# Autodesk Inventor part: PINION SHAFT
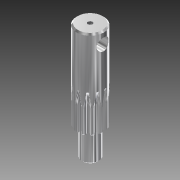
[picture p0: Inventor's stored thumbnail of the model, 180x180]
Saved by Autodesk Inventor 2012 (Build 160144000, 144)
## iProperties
Shininess: 64.0
Length Units: 11269
Angle Units: 11279
Time Units: 11290
Mass Units: 11283
Length Display Precision: 3
Angle Display Precision: 2
Compacted: True
Part Number: PINION SHAFT
Document SubType Name: Modeling
Created: 2003-10
Designer: Autodesk, Inc.
Manufacturer: Standard
Standards Organization: Custom
Mass: 506.446 g
Surface Area: 152.229 cm^2
Volume: 64.5977 cm^3
Density: 7.84 g/cm^3
Material: Steel, High Strength Low Alloy
Density: 0.0
Volumn: 0.0
Area: 0.0
PropertySet Name: Model Information
Control State: 0
Master: False
Checked Out: False
Author: Autodesk, Inc.
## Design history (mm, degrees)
sketch "Sketch1" dims "d4" = 6.7945 (= Big_R), "d5" = 5.54567 (= 2 x little_r)
  geometry: L1 (0, 12.7)-(5.815, 12.7); L2 (5.815, 12.7)-(5.815, 14.817); L3 (5.815, 14.817)-(0, 14.817); L4 (0, 14.817)-(0, 12.7); L5 (-8.163, 9.729)-(5.815, 14.817); L6 (0, 0)-(0, 10.251); L7 (0, 11.934)-(0, 12.7); L8 (0, 11.934)-(0, 10.251); L9 (-0.191, 11.933)-(-0.184, 10.731); L10 (0, 0)-(1.934, 14.69); L11 (0, 0)-(-1.338, 10.163); L12 (0, 0)-(3.923, 9.471); L13 (3.273, 11.477)-(2.955, 10.318); L14 (-0.181, 10.249)-(-0.184, 10.731); A1 r 12.7 centre (0, 0) between (0, 12.7) and (-8.163, 9.729); A2 r 14.817 centre (0, 0) between (0, 14.817) and (1.934, 14.69); A3 r 11.934 centre (0, 0) between (0, 11.934) and (6.294, 10.14); A4 r 10.251 centre (0, 0) between (0, 10.251) and (-0.181, 10.249); A5 r 6.795 centre (6.294, 10.14) between (1.365, 14.817) and (0, 12.7); A6 r 2.773 centre (2.568, 11.654) between (0, 12.7) and (-0.191, 11.933); A7 r 10.251 centre (0, 0) between (-0.651, 10.23) and (-1.338, 10.163); A8 r 0.498 centre (-0.682, 10.728) between (-0.651, 10.23) and (-0.184, 10.731); A9 r 10.251 centre (0, 0) between (3.923, 9.471) and (3.276, 9.713); A10 r 0.498 centre (3.435, 10.186) between (2.955, 10.318) and (3.276, 9.713); A11 r 2.773 centre (0.536, 11.922) between (3.273, 11.477) and (3.287, 12.267); A12 r 6.795 centre (-3.455, 11.423) between (3.287, 12.267) and (2.516, 14.665); A13 r 14.879 centre (0, 0) between (2.516, 14.665) and (1.365, 14.817); 2 further points; 1 other entity
  constraints: 30 point on circle, 28 end point, 13 centre point, 9 coincident, 9 symmetric about line, 4 tangent, 3 point on line, 2 parallel, 2 vertical, 1 collinear, 1 horizontal, 1 perpendicular, 16 other
  dimensions: "d0" = 25.4 diameter of A1 (= Pitch_Diameter); "d1" = 2.11667 distance of L1.end L2.end (= Addendum); "d2" = 20 deg angle of L1 L5 (= Tooth_Form); "d3" = 4.56565 distance of L6.end L3.end (= Whole_Depth); "d6" = 7.5 deg angle of L10 L6 (= mirror_angle); "d7" = 7.5 deg angle of L11 L6 (= mirror_angle); "d8" = 0.49848 radius of A8 (= Root_Fillet)
extrude "Extrusion1" new body sketch "Sketch1" distance "d9" = 25.4; taper "d10" = 0 deg
pattern_circular "Circular Pattern1" dims angle "d13" = 360 deg
sketch "Sketch2"
  geometry: C1 r 14.879 at (0, 0); 1 further point
  constraints: 1 centre point, 1 coincident
  dimensions: "d14" = 29.758 diameter of C1
extrude "Extrusion2" join sketch "Sketch2" distance "d15" = 71.4502; taper "d16" = 0 deg
sketch "Sketch3"
  geometry: C1 r 9.5 at (0, 0); 1 further point
  constraints: 1 centre point, 1 coincident
  dimensions: "d17" = 18.9992 diameter of C1
extrude "Extrusion3" join sketch "Sketch3" distance "d18" = 30.1498; taper "d19" = 0 deg
chamfer "Chamfer1" distance "d20" = 1.5875; stored, may be unused: second distance "d21" = 2, angle "d67" = 45 deg
chamfer "Chamfer2" distance "d22" = 1.5875; stored, may be unused: second distance "d23" = 2, angle "d68" = 45 deg
workplane "Work Plane2"
sketch "Sketch4"
  geometry: L1 (-13.292, 96.85)-(13.292, 96.85) reference; L2 (0, 96.85)-(0, 65.832); C1 r 6.54 at (0, 84.15)
  constraints: 2 end point, 1 centre point, 1 midpoint, 1 perpendicular, 1 point on line
  dimensions: "d26" = 13.081 diameter of C1; "d27" = 12.7 distance from line of L1 C1.centre
extrude "Extrusion4" cut sketch "Sketch4" distance "d28" = 50.8; taper "d29" = 0 deg
workplane "Work Plane3"
sketch "Sketch10"
  geometry: L1 (-5.206, 9.385)-(-5.801, 10.429) reference; L2 (-3.273, 11.477)-(-2.955, 10.318) reference; L3 (-5.801, 10.429)-(-5.206, 9.385); L4 (-2.955, 10.318)-(-3.273, 11.477); L5 (-30.301, 30.745)-(3.482, 44.738); L6 (-8.59, 12.149)-(-2.517, 14.665); L7 (0.184, 10.731)-(0.191, 11.933) reference; L8 (2.904, 11.575)-(2.6, 10.413) reference; L9 (0.191, 11.933)-(0.184, 10.731); L10 (2.904, 11.575)-(2.6, 10.413); L11 (5.524, 9.201)-(6.131, 10.239) reference; L12 (8.303, 8.572)-(7.458, 7.718) reference; L13 (5.524, 9.201)-(6.131, 10.239); L14 (7.458, 7.718)-(8.303, 8.572); L15 (9.385, 5.206)-(10.429, 5.801) reference; L16 (11.477, 3.273)-(10.318, 2.955) reference; L17 (9.385, 5.206)-(10.429, 5.801); L18 (11.477, 3.273)-(10.318, 2.955); A1 r 6.795 centre (3.455, 11.423) between (-2.517, 14.665) and (-3.287, 12.267) reference; A2 r 14.879 centre (0, 0) between (-2.517, 14.665) and (-8.59, 12.149) reference; A3 r 6.795 centre (-10.52, 5.634) between (-6.35, 10.999) and (-8.59, 12.149) reference; A4 r 2.773 centre (-8.051, 8.809) between (-5.801, 10.429) and (-6.35, 10.999) reference; A5 r 0.498 centre (-4.773, 9.632) between (-5.206, 9.385) and (-4.552, 9.185) reference; A6 r 10.251 centre (0, 0) between (-3.276, 9.713) and (-4.552, 9.185) reference; A7 r 0.498 centre (-3.435, 10.186) between (-3.276, 9.713) and (-2.955, 10.318) reference; A8 r 2.773 centre (-0.536, 11.922) between (-3.287, 12.267) and (-3.273, 11.477) reference; A9 r 14.879 centre (0, 0) between (-2.517, 14.665) and (-8.59, 12.149); A10 r 6.795 centre (-10.52, 5.634) between (-6.35, 10.999) and (-8.59, 12.149); A11 r 2.773 centre (-8.051, 8.809) between (-5.801, 10.429) and (-6.35, 10.999); A12 r 0.498 centre (-4.773, 9.632) between (-5.206, 9.385) and (-4.552, 9.185); A13 r 10.251 centre (0, 0) between (-3.276, 9.713) and (-4.552, 9.185); A14 r 6.795 centre (3.455, 11.423) between (-2.517, 14.665) and (-3.287, 12.267); A15 r 2.773 centre (-0.536, 11.922) between (-3.287, 12.267) and (-3.273, 11.477); A16 r 0.498 centre (-3.435, 10.186) between (-3.276, 9.713) and (-2.955, 10.318); A17 r 10.251 centre (0, 0) between (-3.276, 9.713) and (-4.552, 9.185) reference; A18 r 6.795 centre (8.704, 8.165) between (5.153, 13.958) and (3.287, 12.267) reference; A19 r 14.879 centre (0, 0) between (5.153, 13.958) and (-1.365, 14.816) reference; A20 r 6.795 centre (-6.294, 10.14) between (0, 12.7) and (-1.365, 14.816) reference; A21 r 2.773 centre (-2.568, 11.654) between (0.191, 11.933) and (0, 12.7) reference; A22 r 0.498 centre (0.682, 10.728) between (0.184, 10.731) and (0.651, 10.23) reference; A23 r 10.251 centre (0, 0) between (2.019, 10.05) and (0.651, 10.23) reference; A24 r 0.498 centre (2.118, 10.539) between (2.019, 10.05) and (2.6, 10.413) reference; A25 r 2.773 centre (5.497, 10.593) between (3.287, 12.267) and (2.904, 11.575) reference; A26 r 6.795 centre (-6.294, 10.14) between (0, 12.7) and (-1.365, 14.816); A27 r 2.773 centre (-2.568, 11.654) between (0.191, 11.933) and (0, 12.7); A28 r 0.498 centre (0.682, 10.728) between (0.184, 10.731) and (0.651, 10.23); A29 r 0.498 centre (2.118, 10.539) between (2.019, 10.05) and (2.6, 10.413); A30 r 2.773 centre (5.497, 10.593) between (3.287, 12.267) and (2.904, 11.575); A31 r 6.795 centre (8.704, 8.165) between (5.153, 13.958) and (3.287, 12.267); A32 r 14.879 centre (0, 0) between (5.153, 13.958) and (-1.365, 14.816); A33 r 10.251 centre (0, 0) between (2.019, 10.05) and (0.651, 10.23); A34 r 6.795 centre (11.62, 2.72) between (11.442, 9.512) and (8.98, 8.98) reference; A35 r 14.879 centre (0, 0) between (11.442, 9.512) and (6.226, 13.514) reference; A36 r 6.795 centre (-0.381, 11.928) between (6.35, 10.999) and (6.226, 13.514) reference; A37 r 2.773 centre (3.603, 11.377) between (6.131, 10.239) and (6.35, 10.999) reference; A38 r 0.498 centre (5.955, 8.949) between (5.524, 9.201) and (5.679, 8.534) reference; A39 r 10.251 centre (0, 0) between (6.774, 7.694) and (5.679, 8.534) reference; A40 r 0.498 centre (7.103, 8.068) between (6.774, 7.694) and (7.458, 7.718) reference; A41 r 2.773 centre (10.057, 6.425) between (8.98, 8.98) and (8.303, 8.572) reference; A42 r 14.879 centre (0, 0) between (11.442, 9.512) and (6.226, 13.514); A43 r 6.795 centre (-0.381, 11.928) between (6.35, 10.999) and (6.226, 13.514); A44 r 2.773 centre (3.603, 11.377) between (6.131, 10.239) and (6.35, 10.999); A45 r 0.498 centre (5.955, 8.949) between (5.524, 9.201) and (5.679, 8.534); A46 r 0.498 centre (7.103, 8.068) between (6.774, 7.694) and (7.458, 7.718); A47 r 2.773 centre (10.057, 6.425) between (8.98, 8.98) and (8.303, 8.572); A48 r 6.795 centre (11.62, 2.72) between (11.442, 9.512) and (8.98, 8.98); A49 r 10.251 centre (0, 0) between (6.774, 7.694) and (5.679, 8.534); A50 r 6.795 centre (11.423, -3.455) between (14.665, 2.517) and (12.267, 3.287) reference; A51 r 14.879 centre (0, 0) between (14.665, 2.517) and (12.149, 8.59) reference; A52 r 6.795 centre (5.634, 10.52) between (10.999, 6.35) and (12.149, 8.59) reference; A53 r 2.773 centre (8.809, 8.051) between (10.429, 5.801) and (10.999, 6.35) reference; A54 r 0.498 centre (9.632, 4.773) between (9.385, 5.206) and (9.185, 4.552) reference; A55 r 10.251 centre (0, 0) between (9.713, 3.276) and (9.185, 4.552) reference; A56 r 0.498 centre (10.186, 3.435) between (9.713, 3.276) and (10.318, 2.955) reference; A57 r 2.773 centre (11.922, 0.536) between (12.267, 3.287) and (11.477, 3.273) reference; A58 r 10.251 centre (0, 0) between (9.713, 3.276) and (9.185, 4.552); A59 r 0.498 centre (9.632, 4.773) between (9.385, 5.206) and (9.185, 4.552); A60 r 0.498 centre (10.186, 3.435) between (9.713, 3.276) and (10.318, 2.955); A61 r 2.773 centre (11.922, 0.536) between (12.267, 3.287) and (11.477, 3.273); A62 r 2.773 centre (8.809, 8.051) between (10.429, 5.801) and (10.999, 6.35); A63 r 6.795 centre (5.634, 10.52) between (10.999, 6.35) and (12.149, 8.59); A64 r 6.794 centre (11.423, -3.455) between (14.665, 2.517) and (12.267, 3.287)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
  constraints: 66 point on circle, 32 centre point, 30 concentric, 27 tangent, 20 end point, 8 collinear, 1 parallel
  dimensions: "d32" = 40 distance from line of L5 A17.centre
revolve "Revolution1" sketch "Sketch10" stored, may be unused: angle "d33" = 90 deg
sketch "Sketch11"
  geometry: L1 (0.184, 10.731)-(0.191, 11.933) reference; L2 (2.904, 11.575)-(2.6, 10.413) reference; L3 (0.184, 10.731)-(0.191, 11.933); L4 (2.6, 10.413)-(2.904, 11.575); L5 (-8.56, 41.472)-(25.088, 37.042); L6 (-1.365, 14.816)-(5.153, 13.958); C1 r 7.912 at (0, 0) reference; A1 r 6.795 centre (8.704, 8.165) between (5.153, 13.958) and (3.287, 12.267) reference; A2 r 14.879 centre (0, 0) between (5.153, 13.958) and (-1.365, 14.816) reference; A3 r 6.795 centre (-6.294, 10.14) between (0, 12.7) and (-1.365, 14.816) reference; A4 r 2.773 centre (-2.568, 11.654) between (0.191, 11.933) and (0, 12.7) reference; A5 r 0.498 centre (0.682, 10.728) between (0.184, 10.731) and (0.651, 10.23) reference; A6 r 10.251 centre (0, 0) between (2.019, 10.05) and (0.651, 10.23) reference; A7 r 0.498 centre (2.118, 10.539) between (2.019, 10.05) and (2.6, 10.413) reference; A8 r 2.773 centre (5.497, 10.593) between (3.287, 12.267) and (2.904, 11.575) reference; A9 r 14.879 centre (0, 0) between (5.153, 13.958) and (-1.365, 14.816); A10 r 6.795 centre (-6.294, 10.14) between (0, 12.7) and (-1.365, 14.816); A11 r 2.773 centre (-2.568, 11.654) between (0.191, 11.933) and (0, 12.7); A12 r 0.498 centre (0.682, 10.728) between (0.184, 10.731) and (0.651, 10.23); A13 r 10.251 centre (0, 0) between (2.019, 10.05) and (0.651, 10.23); A14 r 6.795 centre (8.704, 8.165) between (5.153, 13.958) and (3.287, 12.267); A15 r 2.773 centre (5.497, 10.593) between (3.287, 12.267) and (2.904, 11.575); A16 r 0.498 centre (2.118, 10.539) between (2.019, 10.05) and (2.6, 10.413)
  constraints: 16 point on circle, 8 centre point, 8 end point, 8 tangent, 6 concentric, 2 collinear, 1 parallel
  dimensions: "d35" = 40 distance from line of C1.centre L5
revolve "Revolution2" sketch "Sketch11" stored, may be unused: angle "d36" = 90 deg
sketch "Sketch12"
  geometry: L1 (5.524, 9.201)-(6.131, 10.239) reference; L2 (8.303, 8.572)-(7.458, 7.718) reference; L3 (8.303, 8.572)-(7.458, 7.718); L4 (5.524, 9.201)-(6.131, 10.239); L5 (37.465, 21.671)-(7.155, 44.928); L6 (11.442, 9.512)-(6.226, 13.514); C1 r 7.912 at (0, 0) reference; A1 r 6.795 centre (11.62, 2.72) between (11.442, 9.512) and (8.98, 8.98) reference; A2 r 14.879 centre (0, 0) between (11.442, 9.512) and (6.226, 13.514) reference; A3 r 6.795 centre (-0.381, 11.928) between (6.35, 10.999) and (6.226, 13.514) reference; A4 r 2.773 centre (3.603, 11.377) between (6.131, 10.239) and (6.35, 10.999) reference; A5 r 0.498 centre (5.955, 8.949) between (5.524, 9.201) and (5.679, 8.534) reference; A6 r 10.251 centre (0, 0) between (6.774, 7.694) and (5.679, 8.534) reference; A7 r 0.498 centre (7.103, 8.068) between (6.774, 7.694) and (7.458, 7.718) reference; A8 r 2.773 centre (10.057, 6.425) between (8.98, 8.98) and (8.303, 8.572) reference; A9 r 14.879 centre (0, 0) between (11.442, 9.512) and (6.226, 13.514); A10 r 0.498 centre (5.955, 8.949) between (5.524, 9.201) and (5.679, 8.534); A11 r 6.795 centre (-0.381, 11.928) between (6.35, 10.999) and (6.226, 13.514); A12 r 2.773 centre (3.603, 11.377) between (6.131, 10.239) and (6.35, 10.999); A13 r 0.498 centre (7.103, 8.068) between (6.774, 7.694) and (7.458, 7.718); A14 r 2.773 centre (10.057, 6.425) between (8.98, 8.98) and (8.303, 8.572); A15 r 6.795 centre (11.62, 2.72) between (11.442, 9.512) and (8.98, 8.98); A16 r 10.251 centre (0, 0) between (6.774, 7.694) and (5.679, 8.534)
  constraints: 16 point on circle, 8 centre point, 8 end point, 7 concentric, 7 tangent, 2 collinear, 1 parallel
  dimensions: "d37" = 40 distance from line of C1.centre L5
revolve "Revolution3" sketch "Sketch12" stored, may be unused: angle "d38" = 90 deg
sketch "Sketch13"
  geometry: L1 (9.385, 5.206)-(10.429, 5.801) reference; L2 (11.477, 3.273)-(10.318, 2.955) reference; L3 (9.385, 5.206)-(10.429, 5.801); L4 (10.318, 2.955)-(11.477, 3.273); L5 (14.665, 2.517)-(12.149, 8.59); L6 (43.302, -0.015)-(26.182, 41.316); C1 r 7.912 at (0, 0) reference; A1 r 6.795 centre (11.423, -3.455) between (14.665, 2.517) and (12.267, 3.287) reference; A2 r 14.879 centre (0, 0) between (14.665, 2.517) and (12.149, 8.59) reference; A3 r 6.795 centre (5.634, 10.52) between (10.999, 6.35) and (12.149, 8.59) reference; A4 r 2.773 centre (8.809, 8.051) between (10.429, 5.801) and (10.999, 6.35) reference; A5 r 0.498 centre (9.632, 4.773) between (9.385, 5.206) and (9.185, 4.552) reference; A6 r 10.251 centre (0, 0) between (9.713, 3.276) and (9.185, 4.552) reference; A7 r 0.498 centre (10.186, 3.435) between (9.713, 3.276) and (10.318, 2.955) reference; A8 r 2.773 centre (11.922, 0.536) between (12.267, 3.287) and (11.477, 3.273) reference; A9 r 6.795 centre (5.634, 10.52) between (10.999, 6.35) and (12.149, 8.59); A10 r 2.773 centre (8.809, 8.051) between (10.429, 5.801) and (10.999, 6.35); A11 r 0.498 centre (9.632, 4.773) between (9.385, 5.206) and (9.185, 4.552); A12 r 0.498 centre (10.186, 3.435) between (9.713, 3.276) and (10.318, 2.955); A13 r 2.773 centre (11.922, 0.536) between (12.267, 3.287) and (11.477, 3.273); A14 r 10.251 centre (0, 0) between (9.713, 3.276) and (9.185, 4.552); A15 r 6.795 centre (11.423, -3.455) between (14.665, 2.517) and (12.267, 3.287); A16 r 14.879 centre (0, 0) between (14.665, 2.517) and (12.149, 8.59)
  constraints: 16 point on circle, 8 centre point, 8 concentric, 8 end point, 2 collinear, 2 tangent, 1 parallel
  dimensions: "d39" = 40 distance from line of C1.centre L6
  node "Projected Loop8"
sketch "Sketch14"
  geometry: L1 (-9.201, 5.524)-(-10.239, 6.131) reference; L2 (-8.572, 8.303)-(-7.718, 7.458) reference; L3 (-9.201, 5.524)-(-10.239, 6.131); L4 (-7.718, 7.458)-(-8.572, 8.303); L5 (-13.514, 6.226)-(-9.512, 11.442); L6 (-43.85, 8.561)-(-20.3, 39.252); C1 r 7.912 at (0, 0) reference; A1 r 6.795 centre (-11.928, -0.381) between (-10.999, 6.35) and (-13.514, 6.226) reference; A2 r 2.773 centre (-11.377, 3.603) between (-10.239, 6.131) and (-10.999, 6.35) reference; A3 r 0.498 centre (-8.949, 5.955) between (-9.201, 5.524) and (-8.534, 5.679) reference; A4 r 10.251 centre (0, 0) between (-7.694, 6.774) and (-8.534, 5.679) reference; A5 r 0.498 centre (-8.068, 7.103) between (-7.694, 6.774) and (-7.718, 7.458) reference; A6 r 2.773 centre (-6.425, 10.057) between (-8.98, 8.98) and (-8.572, 8.303) reference; A7 r 6.795 centre (-2.72, 11.62) between (-9.512, 11.442) and (-8.98, 8.98) reference; A8 r 14.879 centre (0, 0) between (-9.512, 11.442) and (-13.514, 6.226) reference; A9 r 14.879 centre (0, 0) between (-9.512, 11.442) and (-13.514, 6.226); A10 r 0.498 centre (-8.949, 5.955) between (-9.201, 5.524) and (-8.534, 5.679); A11 r 2.773 centre (-11.377, 3.603) between (-10.239, 6.131) and (-10.999, 6.35); A12 r 6.795 centre (-11.928, -0.381) between (-10.999, 6.35) and (-13.514, 6.226); A13 r 6.795 centre (-2.72, 11.62) between (-9.512, 11.442) and (-8.98, 8.98); A14 r 2.773 centre (-6.425, 10.057) between (-8.98, 8.98) and (-8.572, 8.303); A15 r 10.251 centre (0, 0) between (-7.694, 6.774) and (-8.534, 5.679); A16 r 0.498 centre (-8.068, 7.103) between (-7.694, 6.774) and (-7.718, 7.458)
  constraints: 17 point on circle, 8 centre point, 8 end point, 8 tangent, 6 concentric, 2 collinear, 1 parallel
  dimensions: "d40" = 40 distance from line of C1.centre L6
revolve "Revolution5" sketch "Sketch14" stored, may be unused: angle "d42" = 90 deg
revolve "Revolution6" stored, may be unused: angle "d43" = 90 deg
sketch "Sketch15"
  geometry: L1 (10.731, -0.184)-(11.933, -0.191) reference; L2 (11.575, -2.904)-(10.413, -2.6) reference; L3 (10.731, -0.184)-(11.933, -0.191); L4 (10.413, -2.6)-(11.575, -2.904); L5 (13.958, -5.153)-(14.816, 1.365); L6 (42.416, 15.732)-(37.273, -23.332); C1 r 7.912 at (0, 0) reference; A1 r 6.795 centre (8.165, -8.704) between (13.958, -5.153) and (12.267, -3.287) reference; A2 r 14.879 centre (0, 0) between (13.958, -5.153) and (14.816, 1.365) reference; A3 r 6.795 centre (10.14, 6.294) between (12.7, 0) and (14.816, 1.365) reference; A4 r 2.773 centre (11.654, 2.568) between (11.933, -0.191) and (12.7, 0) reference; A5 r 0.498 centre (10.728, -0.682) between (10.731, -0.184) and (10.23, -0.651) reference; A6 r 10.251 centre (0, 0) between (10.05, -2.019) and (10.23, -0.651) reference; A7 r 0.498 centre (10.539, -2.118) between (10.05, -2.019) and (10.413, -2.6) reference; A8 r 2.773 centre (10.593, -5.497) between (12.267, -3.287) and (11.575, -2.904) reference; A9 r 14.879 centre (0, 0) between (13.958, -5.153) and (14.816, 1.365); A10 r 6.795 centre (10.14, 6.294) between (12.7, 0) and (14.816, 1.365); A11 r 2.773 centre (11.654, 2.568) between (11.933, -0.191) and (12.7, 0); A12 r 0.498 centre (10.728, -0.682) between (10.731, -0.184) and (10.23, -0.651); A13 r 10.251 centre (0, 0) between (10.05, -2.019) and (10.23, -0.651); A14 r 0.498 centre (10.539, -2.118) between (10.05, -2.019) and (10.413, -2.6); A15 r 2.773 centre (10.593, -5.497) between (12.267, -3.287) and (11.575, -2.904); A16 r 6.795 centre (8.165, -8.704) between (13.958, -5.153) and (12.267, -3.287)
  constraints: 16 point on circle, 8 centre point, 8 concentric, 8 end point, 5 tangent, 2 collinear, 1 parallel
  dimensions: "d44" = 40 distance from line of C1.centre L6
revolve "Revolution7" sketch "Sketch15" stored, may be unused: angle "d45" = 90 deg
sketch "Sketch16"
  geometry: L1 (9.201, -5.524)-(10.239, -6.131) reference; L2 (8.572, -8.303)-(7.718, -7.458) reference; L3 (9.201, -5.524)-(10.239, -6.131); L4 (7.718, -7.458)-(8.572, -8.303); L5 (9.512, -11.442)-(13.514, -6.226); L6 (22.205, -36.769)-(41.695, -11.369); C1 r 7.912 at (0, 0) reference; A1 r 6.795 centre (2.72, -11.62) between (9.512, -11.442) and (8.98, -8.98) reference; A2 r 14.879 centre (0, 0) between (9.512, -11.442) and (13.514, -6.226) reference; A3 r 6.795 centre (11.928, 0.381) between (10.999, -6.35) and (13.514, -6.226) reference; A4 r 2.773 centre (11.377, -3.603) between (10.239, -6.131) and (10.999, -6.35) reference; A5 r 0.498 centre (8.949, -5.955) between (9.201, -5.524) and (8.534, -5.679) reference; A6 r 10.251 centre (0, 0) between (7.694, -6.774) and (8.534, -5.679) reference; A7 r 0.498 centre (8.068, -7.103) between (7.694, -6.774) and (7.718, -7.458) reference; A8 r 2.773 centre (6.425, -10.057) between (8.98, -8.98) and (8.572, -8.303) reference; A9 r 14.879 centre (0, 0) between (9.512, -11.442) and (13.514, -6.226); A10 r 6.795 centre (11.928, 0.381) between (10.999, -6.35) and (13.514, -6.226); A11 r 2.773 centre (11.377, -3.603) between (10.239, -6.131) and (10.999, -6.35); A12 r 0.498 centre (8.949, -5.955) between (9.201, -5.524) and (8.534, -5.679); A13 r 0.498 centre (8.068, -7.103) between (7.694, -6.774) and (7.718, -7.458); A14 r 2.773 centre (6.425, -10.057) between (8.98, -8.98) and (8.572, -8.303); A15 r 6.795 centre (2.72, -11.62) between (9.512, -11.442) and (8.98, -8.98); A16 r 10.251 centre (0, 0) between (7.694, -6.774) and (8.534, -5.679)
  constraints: 18 point on circle, 9 tangent, 8 centre point, 8 end point, 6 concentric, 2 collinear, 1 parallel
  dimensions: "d51" = 40 distance from line of C1.centre L6
revolve "Revolution8" sketch "Sketch16" stored, may be unused: angle "d48" = 90 deg
sketch "Sketch17"
  geometry: L1 (5.206, -9.385)-(5.801, -10.429) reference; L2 (3.273, -11.477)-(2.955, -10.318) reference; L3 (5.206, -9.385)-(5.801, -10.429); L4 (2.955, -10.318)-(3.273, -11.477); L5 (8.59, -12.149)-(2.517, -14.665); L6 (-1.988, -44.119)-(32.429, -29.863); C1 r 7.912 at (0, 0) reference; A1 r 6.795 centre (10.52, -5.634) between (6.35, -10.999) and (8.59, -12.149) reference; A2 r 2.773 centre (8.051, -8.809) between (5.801, -10.429) and (6.35, -10.999) reference; A3 r 0.498 centre (4.773, -9.632) between (5.206, -9.385) and (4.552, -9.185) reference; A4 r 10.251 centre (0, 0) between (3.276, -9.713) and (4.552, -9.185) reference; A5 r 0.498 centre (3.435, -10.186) between (3.276, -9.713) and (2.955, -10.318) reference; A6 r 2.773 centre (0.536, -11.922) between (3.287, -12.267) and (3.273, -11.477) reference; A7 r 6.795 centre (-3.455, -11.423) between (2.517, -14.665) and (3.287, -12.267) reference; A8 r 14.879 centre (0, 0) between (2.517, -14.665) and (8.59, -12.149) reference; A9 r 14.879 centre (0, 0) between (2.517, -14.665) and (8.59, -12.149); A10 r 6.795 centre (-3.455, -11.423) between (2.517, -14.665) and (3.287, -12.267); A11 r 2.773 centre (0.536, -11.922) between (3.287, -12.267) and (3.273, -11.477); A12 r 0.498 centre (3.435, -10.186) between (3.276, -9.713) and (2.955, -10.318); A13 r 0.498 centre (4.773, -9.632) between (5.206, -9.385) and (4.552, -9.185); A14 r 6.795 centre (10.52, -5.634) between (6.35, -10.999) and (8.59, -12.149); A15 r 2.773 centre (8.051, -8.809) between (5.801, -10.429) and (6.35, -10.999); A16 r 10.251 centre (0, 0) between (3.276, -9.713) and (4.552, -9.185)
  constraints: 17 point on circle, 8 centre point, 8 end point, 7 concentric, 5 tangent, 2 collinear, 1 parallel
  dimensions: "d49" = 40 distance from line of C1.centre L6
revolve "Revolution9" sketch "Sketch17" stored, may be unused: angle "d50" = 90 deg
sketch "Sketch18"
  geometry: L1 (-0.184, -10.731)-(-0.191, -11.933) reference; L2 (-2.904, -11.575)-(-2.6, -10.413) reference; L3 (-0.184, -10.731)-(-0.191, -11.933); L4 (-2.6, -10.413)-(-2.904, -11.575); L5 (-5.153, -13.958)-(1.365, -14.816); L6 (18.309, -42.756)-(-25.099, -37.041); C1 r 7.912 at (0, 0) reference; A1 r 6.795 centre (6.294, -10.14) between (0, -12.7) and (1.365, -14.816) reference; A2 r 2.773 centre (2.568, -11.654) between (-0.191, -11.933) and (0, -12.7) reference; A3 r 0.498 centre (-0.682, -10.728) between (-0.184, -10.731) and (-0.651, -10.23) reference; A4 r 10.251 centre (0, 0) between (-2.019, -10.05) and (-0.651, -10.23) reference; A5 r 0.498 centre (-2.118, -10.539) between (-2.019, -10.05) and (-2.6, -10.413) reference; A6 r 2.773 centre (-5.497, -10.593) between (-3.287, -12.267) and (-2.904, -11.575) reference; A7 r 6.795 centre (-8.704, -8.165) between (-5.153, -13.958) and (-3.287, -12.267) reference; A8 r 14.879 centre (0, 0) between (-5.153, -13.958) and (1.365, -14.816) reference; A9 r 14.879 centre (0, 0) between (-5.153, -13.958) and (1.365, -14.816); A10 r 6.795 centre (6.294, -10.14) between (0, -12.7) and (1.365, -14.816); A11 r 0.498 centre (-0.682, -10.728) between (-0.184, -10.731) and (-0.651, -10.23); A12 r 2.773 centre (2.568, -11.654) between (-0.191, -11.933) and (0, -12.7); A13 r 6.795 centre (-8.704, -8.165) between (-5.153, -13.958) and (-3.287, -12.267); A14 r 2.773 centre (-5.497, -10.593) between (-3.287, -12.267) and (-2.904, -11.575); A15 r 0.498 centre (-2.118, -10.539) between (-2.019, -10.05) and (-2.6, -10.413); A16 r 10.251 centre (0, 0) between (-2.019, -10.05) and (-0.651, -10.23)
  constraints: 16 point on circle, 9 tangent, 8 centre point, 8 end point, 6 concentric, 2 collinear, 1 parallel
  dimensions: "d52" = 40 distance from line of L6 C1.centre
revolve "Revolution10" sketch "Sketch18" stored, may be unused: angle "d53" = 90 deg
sketch "Sketch19"
  geometry: L1 (-5.524, -9.201)-(-6.131, -10.239) reference; L2 (-8.303, -8.572)-(-7.458, -7.718) reference; L3 (-5.524, -9.201)-(-6.131, -10.239); L4 (-7.458, -7.718)-(-8.303, -8.572); L5 (-11.442, -9.512)-(-6.226, -13.514); L6 (-14.257, -39.479)-(-36.918, -22.091); C1 r 7.912 at (0, 0) reference; A1 r 6.795 centre (0.381, -11.928) between (-6.35, -10.999) and (-6.226, -13.514) reference; A2 r 2.773 centre (-3.603, -11.377) between (-6.131, -10.239) and (-6.35, -10.999) reference; A3 r 0.498 centre (-5.955, -8.949) between (-5.524, -9.201) and (-5.679, -8.534) reference; A4 r 10.251 centre (0, 0) between (-6.774, -7.694) and (-5.679, -8.534) reference; A5 r 0.498 centre (-7.103, -8.068) between (-6.774, -7.694) and (-7.458, -7.718) reference; A6 r 2.773 centre (-10.057, -6.425) between (-8.98, -8.98) and (-8.303, -8.572) reference; A7 r 6.795 centre (-11.62, -2.72) between (-11.442, -9.512) and (-8.98, -8.98) reference; A8 r 14.879 centre (0, 0) between (-11.442, -9.512) and (-6.226, -13.514) reference; A9 r 14.879 centre (0, 0) between (-11.442, -9.512) and (-6.226, -13.514); A10 r 6.795 centre (0.381, -11.928) between (-6.35, -10.999) and (-6.226, -13.514); A11 r 0.498 centre (-5.955, -8.949) between (-5.524, -9.201) and (-5.679, -8.534); A12 r 0.498 centre (-7.103, -8.068) between (-6.774, -7.694) and (-7.458, -7.718); A13 r 6.795 centre (-11.62, -2.72) between (-11.442, -9.512) and (-8.98, -8.98); A14 r 10.251 centre (0, 0) between (-6.774, -7.694) and (-5.679, -8.534); A15 r 2.773 centre (-10.057, -6.425) between (-8.98, -8.98) and (-8.303, -8.572); A16 r 2.773 centre (-3.603, -11.377) between (-6.131, -10.239) and (-6.35, -10.999)
  constraints: 16 point on circle, 11 tangent, 8 centre point, 8 end point, 5 concentric, 2 collinear, 1 parallel
  dimensions: "d54" = 40 distance from line of C1.centre L6
revolve "Revolution11" sketch "Sketch19" stored, may be unused: angle "d55" = 90 deg
sketch "Sketch20"
  geometry: L1 (-9.385, -5.206)-(-10.429, -5.801) reference; L2 (-11.477, -3.273)-(-10.318, -2.955) reference; L3 (-9.385, -5.206)-(-10.429, -5.801); L4 (-10.318, -2.955)-(-11.477, -3.273); L5 (-14.665, -2.517)-(-12.149, -8.59); L6 (-31.542, -28.377)-(-43.268, -0.067); C1 r 7.912 at (0, 0) reference; A1 r 6.795 centre (-5.634, -10.52) between (-10.999, -6.35) and (-12.149, -8.59) reference; A2 r 2.773 centre (-8.809, -8.051) between (-10.429, -5.801) and (-10.999, -6.35) reference; A3 r 0.498 centre (-9.632, -4.773) between (-9.385, -5.206) and (-9.185, -4.552) reference; A4 r 10.251 centre (0, 0) between (-9.713, -3.276) and (-9.185, -4.552) reference; A5 r 0.498 centre (-10.186, -3.435) between (-9.713, -3.276) and (-10.318, -2.955) reference; A6 r 2.773 centre (-11.922, -0.536) between (-12.267, -3.287) and (-11.477, -3.273) reference; A7 r 6.795 centre (-11.423, 3.455) between (-14.665, -2.517) and (-12.267, -3.287) reference; A8 r 14.879 centre (0, 0) between (-14.665, -2.517) and (-12.149, -8.59) reference; A9 r 14.879 centre (0, 0) between (-14.665, -2.517) and (-12.149, -8.59); A10 r 6.795 centre (-11.423, 3.455) between (-14.665, -2.517) and (-12.267, -3.287); A11 r 6.795 centre (-5.634, -10.52) between (-10.999, -6.35) and (-12.149, -8.59); A12 r 0.498 centre (-9.632, -4.773) between (-9.385, -5.206) and (-9.185, -4.552); A13 r 0.498 centre (-10.186, -3.435) between (-9.713, -3.276) and (-10.318, -2.955); A14 r 2.773 centre (-11.922, -0.536) between (-12.267, -3.287) and (-11.477, -3.273); A15 r 2.773 centre (-8.809, -8.051) between (-10.429, -5.801) and (-10.999, -6.35); A16 r 10.251 centre (0, 0) between (-9.713, -3.276) and (-9.185, -4.552)
  constraints: 16 point on circle, 8 centre point, 8 end point, 7 concentric, 7 tangent, 2 collinear, 1 parallel
  dimensions: "d56" = 40 distance from line of C1.centre L6
revolve "Revolution12" sketch "Sketch20" stored, may be unused: angle "d57" = 90 deg
sketch "Sketch21"
  geometry: L1 (-10.731, 0.184)-(-11.933, 0.191) reference; L2 (-11.575, 2.904)-(-10.413, 2.6) reference; L3 (-10.731, 0.184)-(-11.933, 0.191); L4 (-10.413, 2.6)-(-11.575, 2.904); L5 (-13.958, 5.153)-(-14.816, -1.365); L6 (-37.606, 20.805)-(-41.538, -9.057); C1 r 7.912 at (0, 0) reference; A1 r 6.795 centre (-10.14, -6.294) between (-12.7, 0) and (-14.816, -1.365) reference; A2 r 2.773 centre (-11.654, -2.568) between (-11.933, 0.191) and (-12.7, 0) reference; A3 r 0.498 centre (-10.728, 0.682) between (-10.731, 0.184) and (-10.23, 0.651) reference; A4 r 10.251 centre (0, 0) between (-10.05, 2.019) and (-10.23, 0.651) reference; A5 r 0.498 centre (-10.539, 2.118) between (-10.05, 2.019) and (-10.413, 2.6) reference; A6 r 2.773 centre (-10.593, 5.497) between (-12.267, 3.287) and (-11.575, 2.904) reference; A7 r 6.795 centre (-8.165, 8.704) between (-13.958, 5.153) and (-12.267, 3.287) reference; A8 r 14.879 centre (0, 0) between (-13.958, 5.153) and (-14.816, -1.365) reference; A9 r 14.879 centre (0, 0) between (-13.958, 5.153) and (-14.816, -1.365); A10 r 6.795 centre (-10.14, -6.294) between (-12.7, 0) and (-14.816, -1.365); A11 r 0.498 centre (-10.728, 0.682) between (-10.731, 0.184) and (-10.23, 0.651); A12 r 0.498 centre (-10.539, 2.118) between (-10.05, 2.019) and (-10.413, 2.6); A13 r 2.773 centre (-10.593, 5.497) between (-12.267, 3.287) and (-11.575, 2.904); A14 r 2.773 centre (-11.654, -2.568) between (-11.933, 0.191) and (-12.7, 0); A15 r 6.795 centre (-8.165, 8.704) between (-13.958, 5.153) and (-12.267, 3.287); A16 r 10.251 centre (0, 0) between (-10.05, 2.019) and (-10.23, 0.651)
  constraints: 16 point on circle, 8 centre point, 8 end point, 6 concentric, 6 tangent, 2 collinear, 1 parallel
  dimensions: "d58" = 40 distance from line of C1.centre L6
revolve "Revolution13" sketch "Sketch21" stored, may be unused: angle "d59" = 90 deg
sketch "Sketch22"
  geometry: C1 r 13.292 at (0, 0) reference; 1 further point
  constraints: 1 coincident
hole "Hole1" sketch "Sketch22" at (0, 0) diameter "d60" = 4.978; stored, may be unused: countersink angle "d64" = 82 deg, drill point angle "d66" = 118 deg; dims "d61" = 6, "d62" = 4, "d63" = 2, "d65" = 8
body "Solid1"
node "Projected Loop2"
node "Projected Loop3"
node "Projected Loop4"
node "Projected Loop5"
node "Projected Loop6"
node "Projected Loop7"
node "Projected Loop9"
node "Projected Loop10"
node "Projected Loop11"
node "Projected Loop12"
node "Projected Loop13"
node "Projected Loop14"
node "Projected Loop15"
node "Projected Loop16"
node "Projected Loop17"
other parameters: "Tooth_Form" = 20 deg [user parameter; used in 1 equation term], "Pitch_Diameter" = 25.4 [user parameter; used in 1 equation term], "Addendum" = 2.11667 [user parameter; used in 1 equation term], "Whole_Depth" = 4.56565 [user parameter; used in 1 equation term], "Big_R" = 6.7945 [user parameter; used in 1 equation term], "little_r" = 2.77283 [user parameter; used in 1 equation term], "Root_Fillet" = 0.49848 [user parameter; used in 1 equation term], "mirror_angle" = 7.5 deg [user parameter; used in 2 equation terms], "d25" = 16.75
